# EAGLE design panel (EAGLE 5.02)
LAST_EDIT: 15.07; TITLE: xMedia P. - Sensors

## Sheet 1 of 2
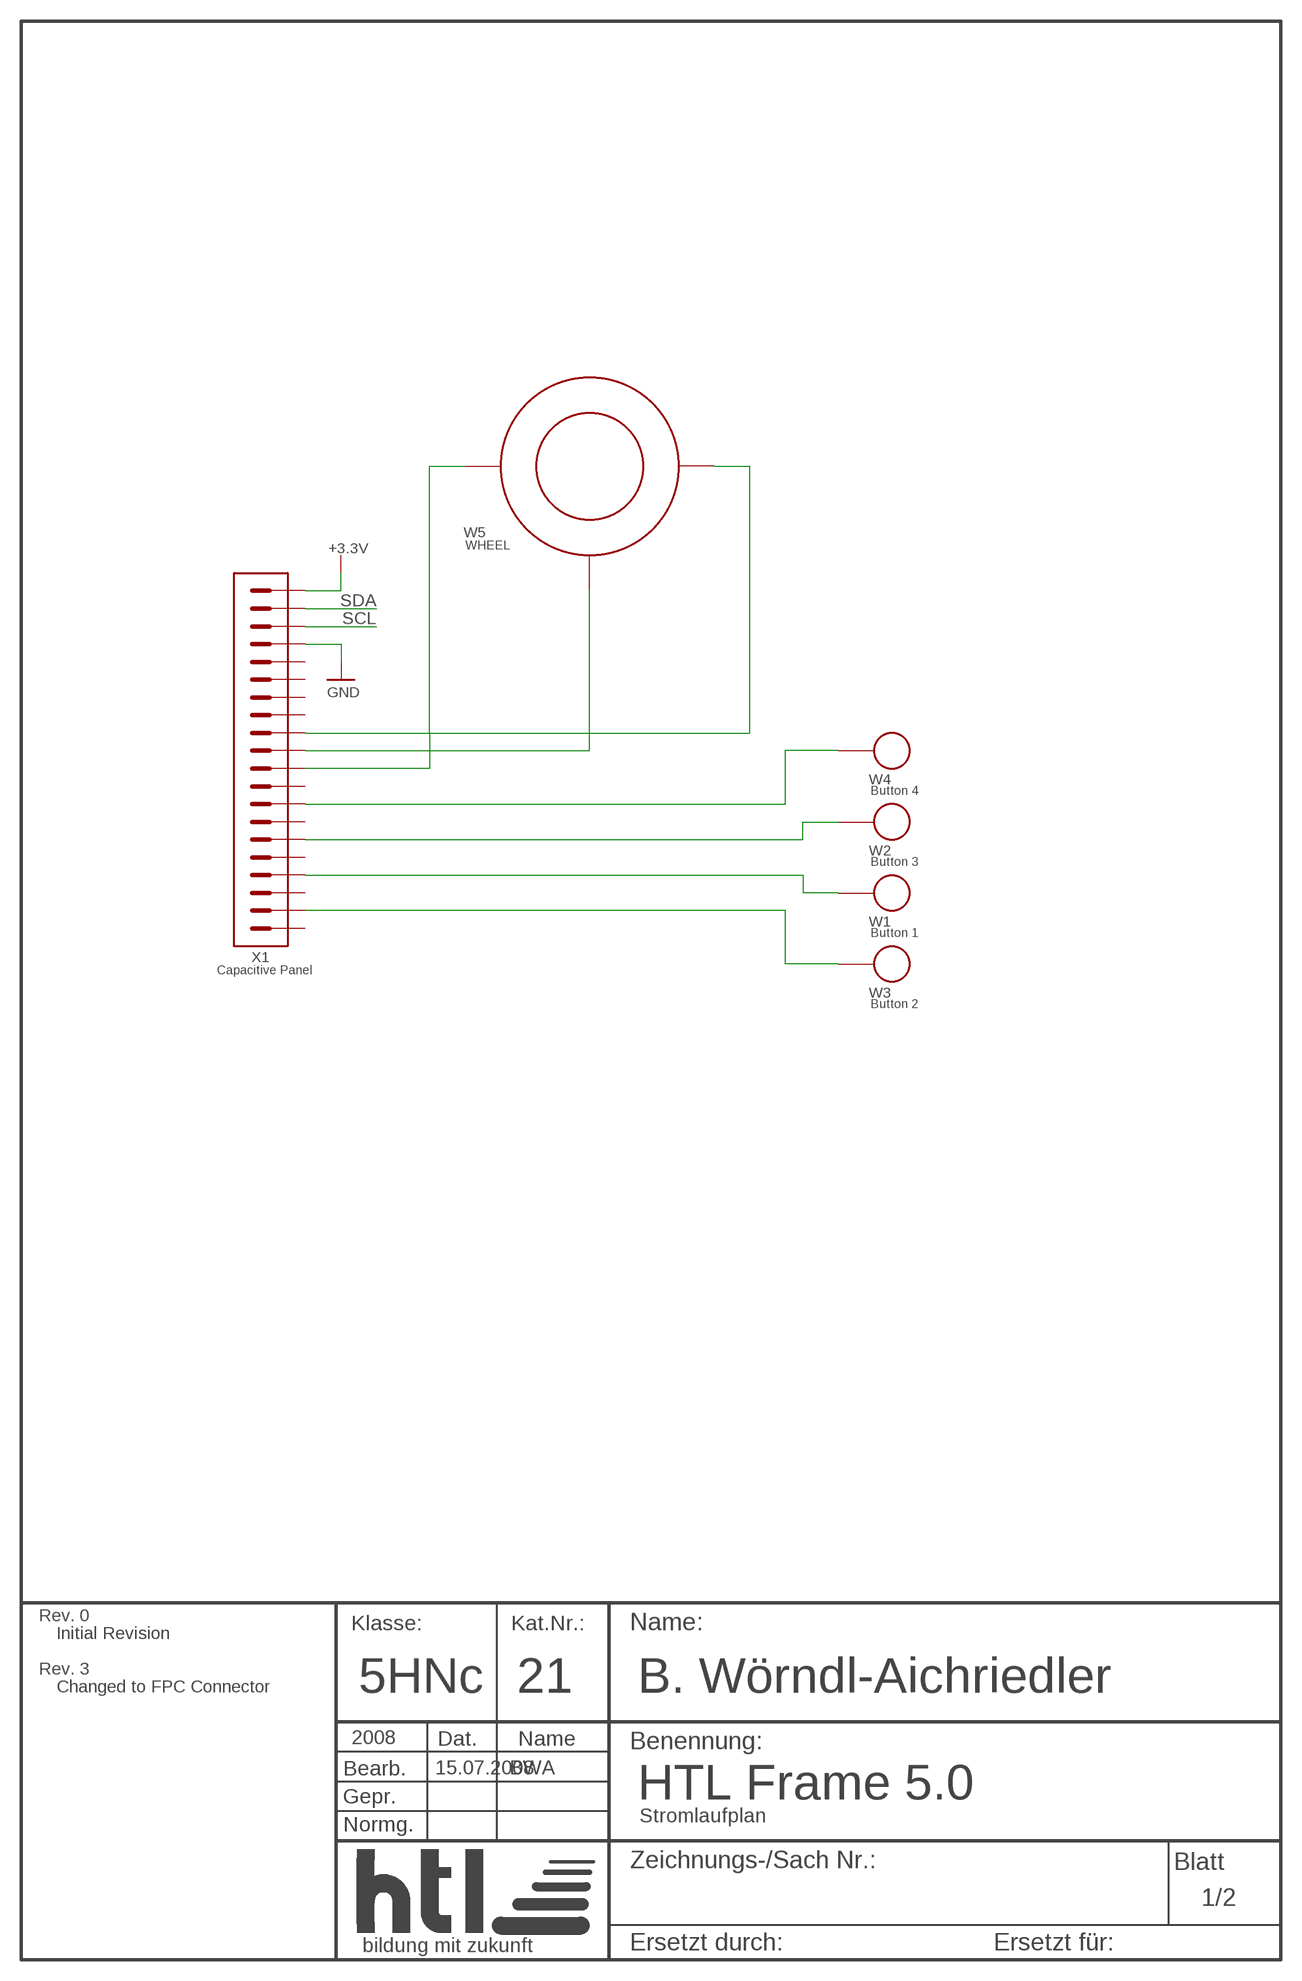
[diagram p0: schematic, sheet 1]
U$1 (HTL-FRAME-A4): CAT_NO: 21; CLASS: 5HNc; LAST_EDIT: 15.07.2008; SHORTNAME: BWA; SUBTITLE: Stromlaufplan; TITLE: HTL Frame 5.0; USERNAME: B. Wörndl-Aichriedler; YEAR: 2008

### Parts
W1  Button 1  CAP_BTN  [CAP_BTN]
W2  Button 3  CAP_BTN  [CAP_BTN]
W3  Button 2  CAP_BTN  [CAP_BTN]
W4  Button 4  CAP_BTN  [CAP_BTN]
W5  WHEEL  CAP_WHEEL  [CAP_WHEEL]
X1  Capacitive Panel  FPC-20-1MM  [FPC-20-1MM]

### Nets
+3.3V: X1.P$1 ; also sheet 2
GND: X1.P$4 ; also sheet 2
N$49: W5.1 X1.P$11
N$50: W5.3 X1.P$10
N$51: W5.2 X1.P$9
N$52: W4.P$1 X1.P$13
N$53: W2.P$1 X1.P$15
N$54: W1.P$1 X1.P$17
N$55: W3.P$1 X1.P$19
SCL: X1.P$3 ; also sheet 2
SDA: X1.P$2 ; also sheet 2
Unconnected: X1.P$5 X1.P$6 X1.P$7 X1.P$8 X1.P$12 X1.P$14 X1.P$16 X1.P$18 X1.P$20

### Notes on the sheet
- Rev. 0
- Initial Revision
- Rev. 3
- Changed to FPC Connector

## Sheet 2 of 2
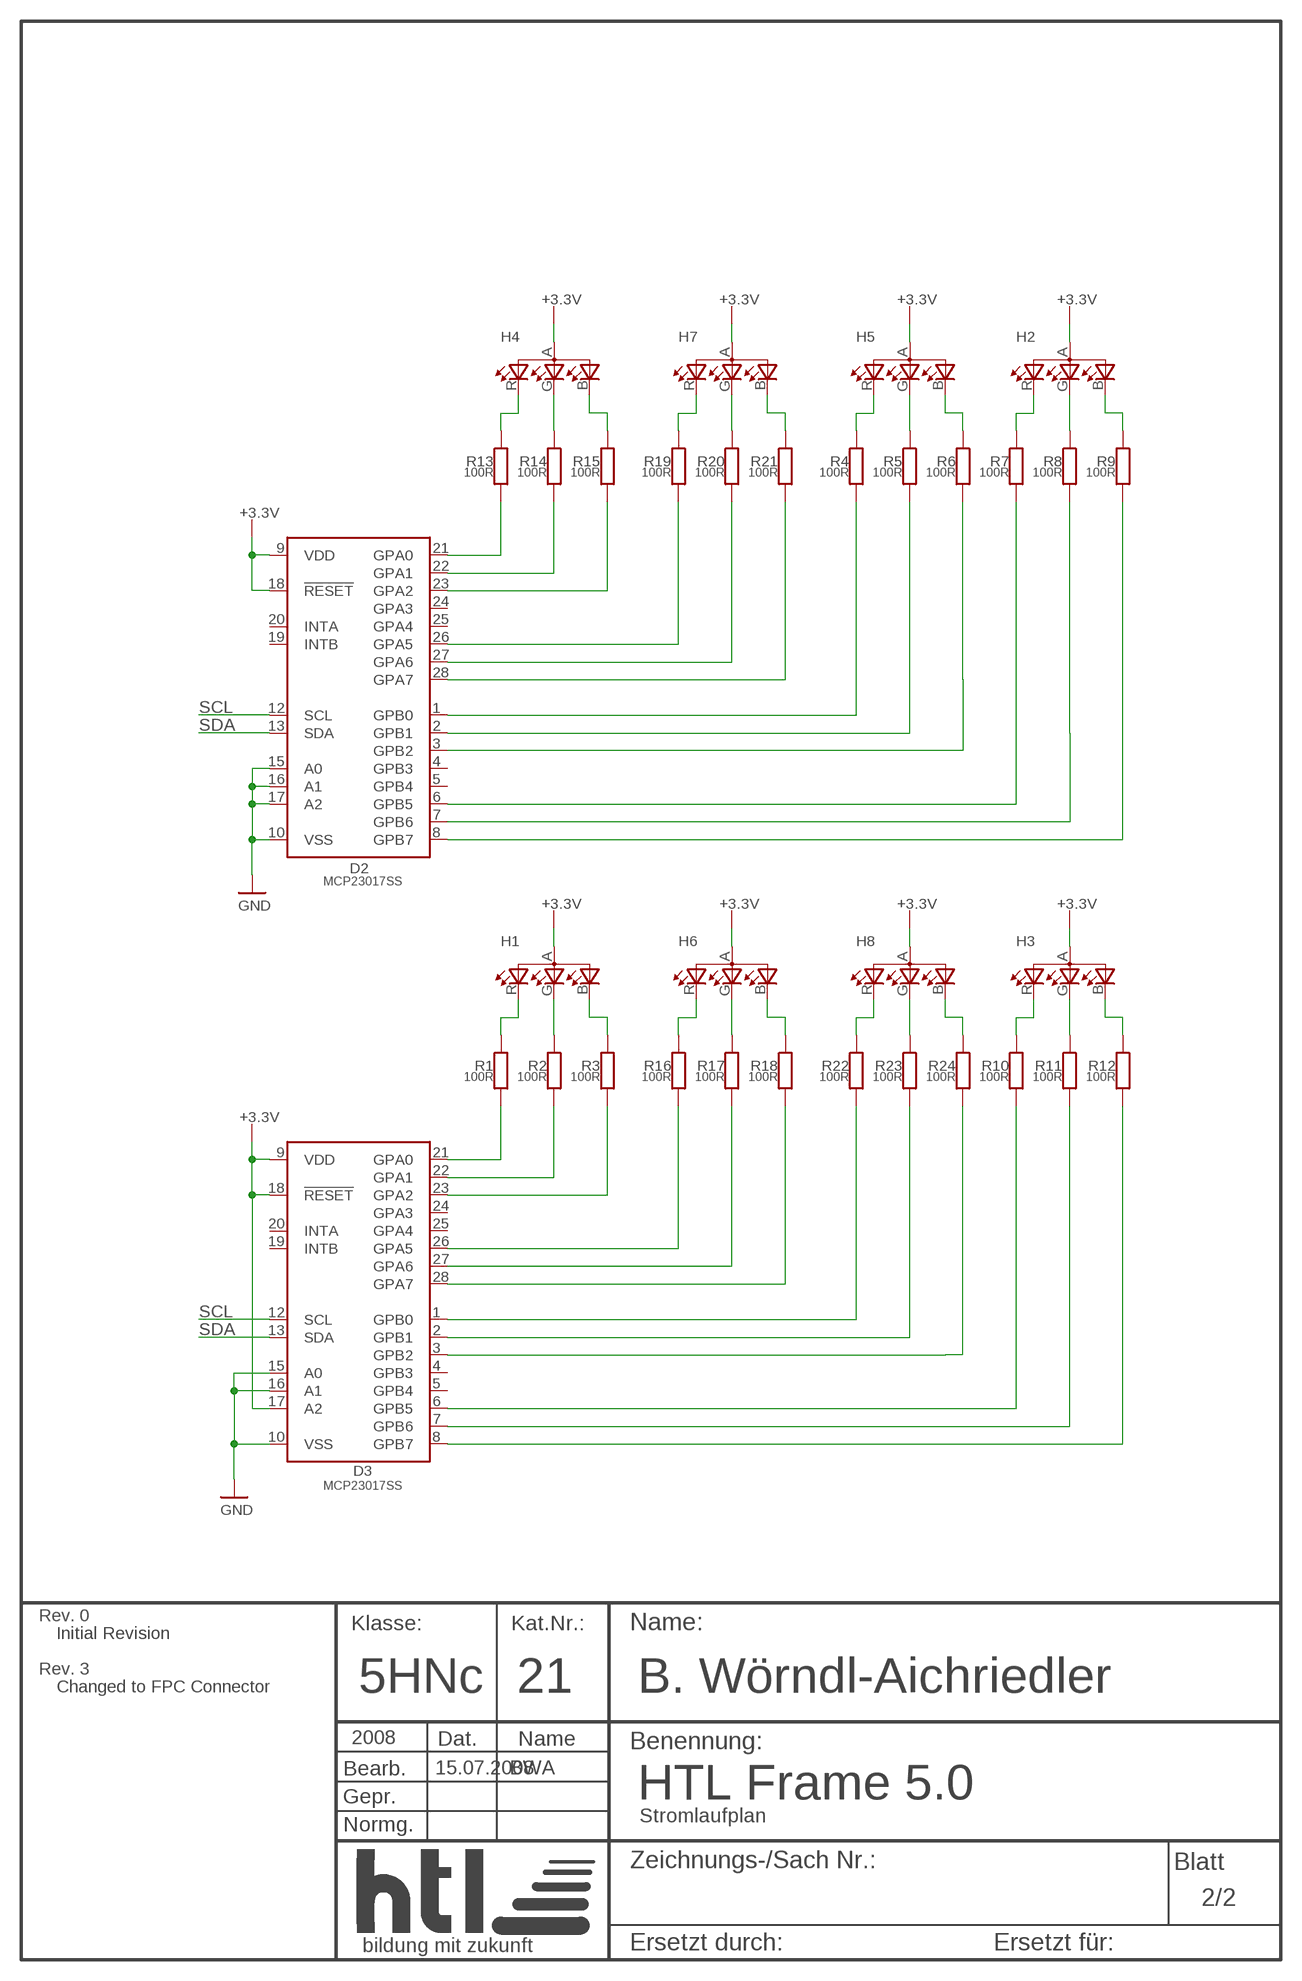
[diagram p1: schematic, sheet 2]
U$3 (HTL-FRAME-A4): CAT_NO: 21; CLASS: 5HNc; LAST_EDIT: 15.07.2008; SHORTNAME: BWA; SUBTITLE: Stromlaufplan; TITLE: HTL Frame 5.0; USERNAME: B. Wörndl-Aichriedler; YEAR: 2008

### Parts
D2  MCP23017SS  [SSOP28]
D3  MCP23017SS  [SSOP28]
H1  TOPLED-3BOTTOM_THRU  [P-LCC-4-SPECIAL]
H2  TOPLED-3BOTTOM_THRU  [P-LCC-4-SPECIAL]
H3  TOPLED-3BOTTOM_THRU  [P-LCC-4-SPECIAL]
H4  TOPLED-3BOTTOM_THRU  [P-LCC-4-SPECIAL]
H5  TOPLED-3BOTTOM_THRU  [P-LCC-4-SPECIAL]
H6  TOPLED-3BOTTOM_THRU  [P-LCC-4-SPECIAL]
H7  TOPLED-3BOTTOM_THRU  [P-LCC-4-SPECIAL]
H8  TOPLED-3BOTTOM_THRU  [P-LCC-4-SPECIAL]
R1  100R  R-EU_R0805  [R0805]
R2  100R  R-EU_R0805  [R0805]
R3  100R  R-EU_R0805  [R0805]
R4  100R  R-EU_R0805  [R0805]
R5  100R  R-EU_R0805  [R0805]
R6  100R  R-EU_R0805  [R0805]
R7  100R  R-EU_R0805  [R0805]
R8  100R  R-EU_R0805  [R0805]
R9  100R  R-EU_R0805  [R0805]
R10  100R  R-EU_R0805  [R0805]
R11  100R  R-EU_R0805  [R0805]
R12  100R  R-EU_R0805  [R0805]
R13  100R  R-EU_R0805  [R0805]
R14  100R  R-EU_R0805  [R0805]
R15  100R  R-EU_R0805  [R0805]
R16  100R  R-EU_R0805  [R0805]
R17  100R  R-EU_R0805  [R0805]
R18  100R  R-EU_R0805  [R0805]
R19  100R  R-EU_R0805  [R0805]
R20  100R  R-EU_R0805  [R0805]
R21  100R  R-EU_R0805  [R0805]
R22  100R  R-EU_R0805  [R0805]
R23  100R  R-EU_R0805  [R0805]
R24  100R  R-EU_R0805  [R0805]

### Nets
+3.3V: D2.9(VDD) D2.18(!RESET) D3.9(VDD) D3.17(A2) D3.18(!RESET) H1.A(A2) H2.A(A2) H3.A(A2) H4.A(A2) H5.A(A2) H6.A(A2) H7.A(A2) H8.A(A2) ; also sheet 1
GND: D2.10(VSS) D2.15(A0) D2.16(A1) D2.17(A2) D3.10(VSS) D3.15(A0) D3.16(A1) ; also sheet 1
N$1: H1.R(CRED) R1.1
N$2: H1.G(CGREEN) R2.1
N$3: H1.B(CBLUE) R3.1
N$4: D3.21(GPA0) R1.2
N$5: D3.22(GPA1) R2.2
N$6: D3.23(GPA2) R3.2
N$7: H5.R(CRED) R4.1
N$8: H5.G(CGREEN) R5.1
N$9: H5.B(CBLUE) R6.1
N$10: D2.1(GPB0) R4.2
N$11: D2.2(GPB1) R5.2
N$12: D2.3(GPB2) R6.2
N$13: H2.R(CRED) R7.1
N$14: H2.G(CGREEN) R8.1
N$15: H2.B(CBLUE) R9.1
N$16: D2.6(GPB5) R7.2
N$17: D2.7(GPB6) R8.2
N$18: D2.8(GPB7) R9.2
N$19: H3.R(CRED) R10.1
N$20: H3.G(CGREEN) R11.1
N$21: H3.B(CBLUE) R12.1
N$22: D3.6(GPB5) R10.2
N$23: D3.7(GPB6) R11.2
N$24: D3.8(GPB7) R12.2
N$25: H4.R(CRED) R13.1
N$26: H4.G(CGREEN) R14.1
N$27: H4.B(CBLUE) R15.1
N$28: D2.21(GPA0) R13.2
N$29: D2.22(GPA1) R14.2
N$30: D2.23(GPA2) R15.2
N$31: H6.R(CRED) R16.1
N$32: H6.G(CGREEN) R17.1
N$33: H6.B(CBLUE) R18.1
N$34: D3.26(GPA5) R16.2
N$35: D3.27(GPA6) R17.2
N$36: D3.28(GPA7) R18.2
N$37: H7.R(CRED) R19.1
N$38: H7.G(CGREEN) R20.1
N$39: H7.B(CBLUE) R21.1
N$40: D2.26(GPA5) R19.2
N$41: D2.27(GPA6) R20.2
N$42: D2.28(GPA7) R21.2
N$43: H8.R(CRED) R22.1
N$44: H8.G(CGREEN) R23.1
N$45: H8.B(CBLUE) R24.1
N$46: D3.1(GPB0) R22.2
N$47: D3.2(GPB1) R23.2
N$48: D3.3(GPB2) R24.2
SCL: D2.12(SCL) D3.12(SCL) ; also sheet 1
SDA: D2.13(SDA) D3.13(SDA) ; also sheet 1
Unconnected: D2.4(GPB3) D2.5(GPB4) D2.19(INTB) D2.20(INTA) D2.24(GPA3) D2.25(GPA4) D3.4(GPB3) D3.5(GPB4) D3.19(INTB) D3.20(INTA) D3.24(GPA3) D3.25(GPA4)

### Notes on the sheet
- Rev. 0
- Initial Revision
- Rev. 3
- Changed to FPC Connector

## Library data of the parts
D2 D3 = xmedia:MCP23017: http://ww1.microchip.com/downloads/en/DeviceDoc/21952a.pdf Source: http://ww1.microchip.com/downloads/en/DeviceDoc/21952a.pdf
H1-H8 = xmedia:TOPLED-3: OSRAM - Hyper Multi TOPLED® (RGB) LB E673, LV E673, LT E673 - Power TOPLED® Enhanced optical Power LED (HOP2000) LS E67B, LA E67B, LO E67B, LY E67B - Hyper Multi TOPLED® Enhanced optical Power LED (HOP2000 / ATON®) LATB T66B - Hyper Multi TOPLED® Hyper-Bright LED LATB T686 Source: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
R1-R24 = xmedia-rcl:R-EU_: RESISTOR, European symbol
W1-W4 = xmedia:CAP_BTN
W5 = xmedia:CAP_WHEEL
X1 = xmedia:FPC-20-1MM

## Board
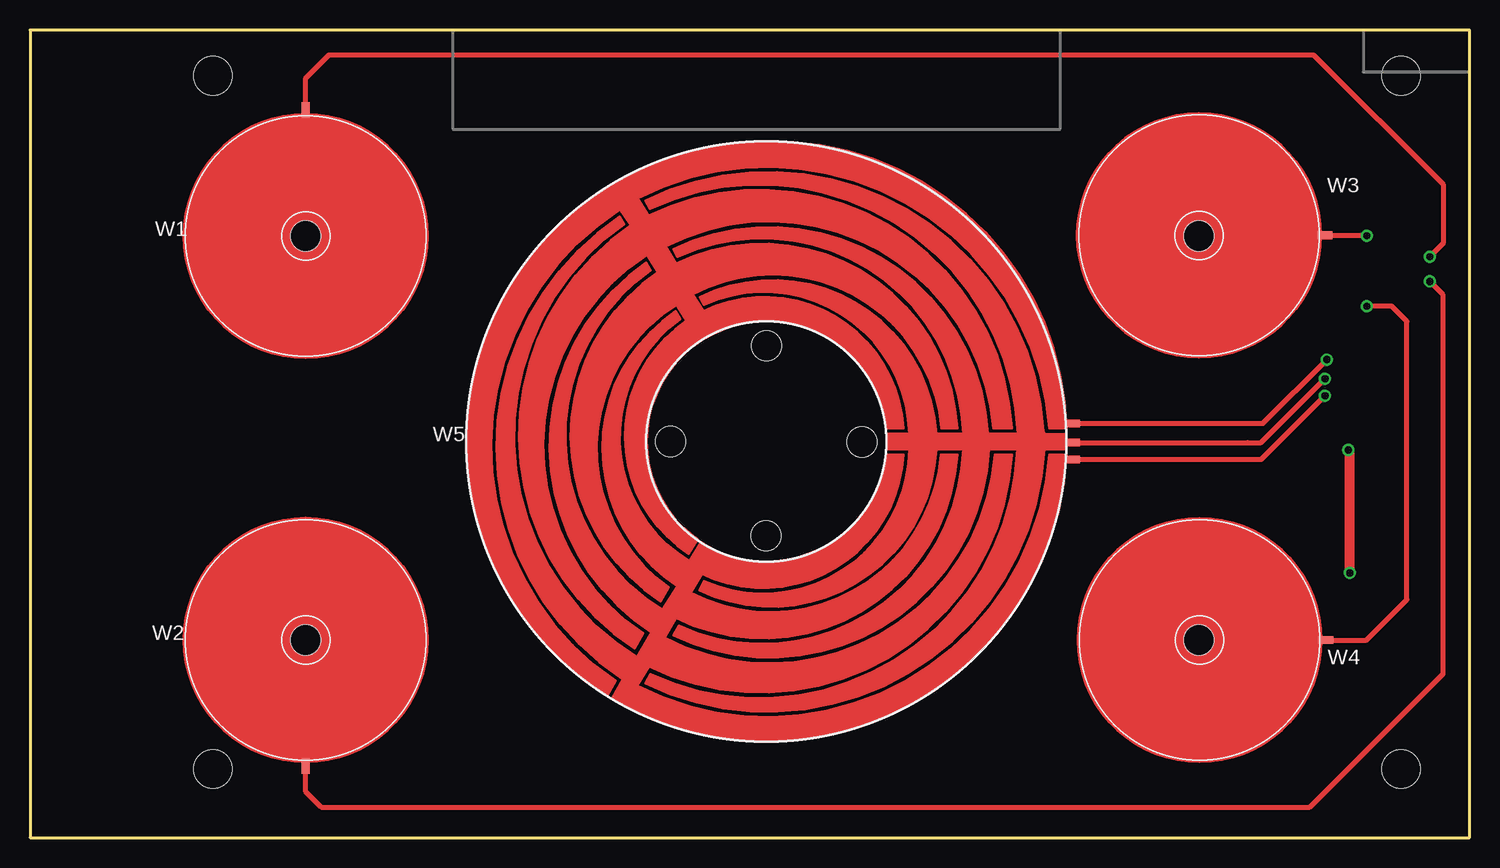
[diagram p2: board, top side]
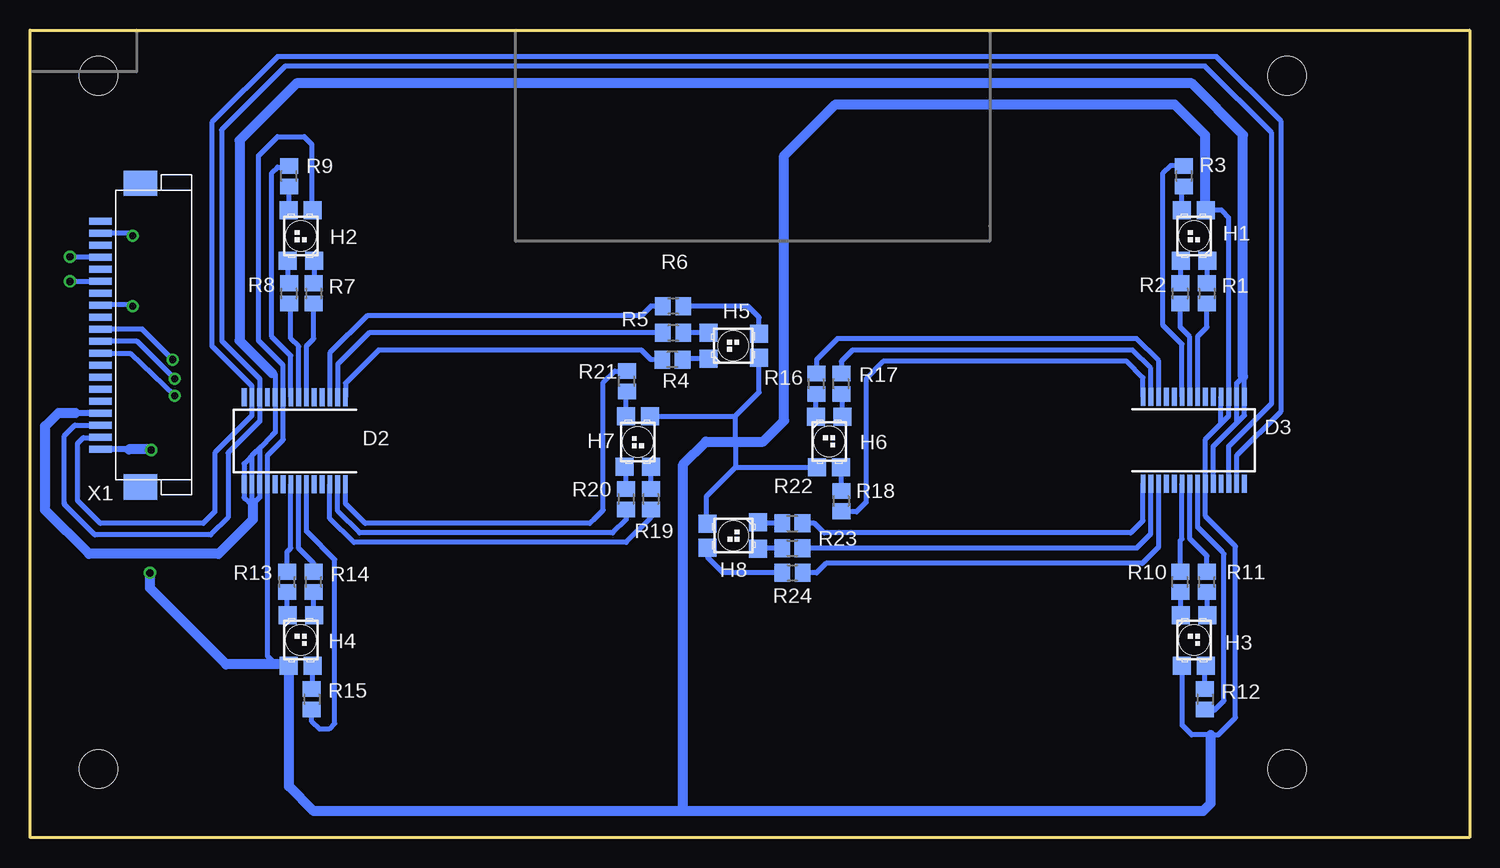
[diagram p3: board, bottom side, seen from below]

Size 120.02 x 67.31 mm. Coordinates in mm from the lower left corner, seen from the top.
Outline: 0,0 120.02,0 120.02,67.31 0,67.31 0,0
Copper layers (1+16): Top 0.035mm / dielectric 1.6mm / Bottom 0.035mm
Design rules "multipcb": minimum track width 6mil, minimum drill 0.4mm, track to track 6mil, track to pad 6mil, pad to pad 6mil, via to via 6mil, smd to smd 6mil, copper to edge 20mil, drill to drill 10mil, minimum pad ring 8mil, minimum via ring 8mil, stop-mask expansion 4mil, vias tented up to drill 18mil, thermal gap 10mil
Holes 3.2 mm at 114.3,63.5 15.24,63.5 15.24,5.71 114.3,5.71

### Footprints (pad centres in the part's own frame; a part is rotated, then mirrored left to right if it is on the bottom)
SSOP28 = smd 0.4 x 1.5: 1 -4.225,-3.625; 2 -3.575,-3.625; 3 -2.925,-3.625; 4 -2.275,-3.625; 5 -1.625,-3.625; 6 -0.975,-3.625; 7 -0.325,-3.625; 8 0.325,-3.625; 9 0.975,-3.625; 10 1.625,-3.625; 11 2.275,-3.625; 12 2.925,-3.625; 13 3.575,-3.625; 14 4.225,-3.625; 15 4.225,3.625; 16 3.575,3.625; 17 2.925,3.625; 18 2.275,3.625; 19 1.625,3.625; 20 0.975,3.625; 21 0.325,3.625; 22 -0.325,3.625; 23 -0.975,3.625; 24 -1.625,3.625; 25 -2.275,3.625; 26 -2.925,3.625; 27 -3.575,3.625; 28 -4.225,3.625
P-LCC-4-SPECIAL = smd 1.5 x 1.5 bottom: A -1,2.15; B 1,2.15; G 1.1,-2.05; R -1.1,-2.05 | hole 2.5: 0,0
R0805 = smd 1.3 x 1.5: 1 -0.85,0; 2 0.85,0
CAP_BTN = smd 1.27 x 0.635: P$1 -10.5,0
CAP_WHEEL = smd 0.635 x 1.27: 1 -1.5,25.5; 2 1.5,25.5; 3 0.1,25.5
FPC-20-1MM = smd 0.6 x 1.9: P$1 0,0; P$2 1,0; P$3 2,0; P$4 3,0; P$5 4,0; P$6 5,0; P$7 6,0; P$8 7,0; P$9 8,0; P$10 9,0; P$11 10,0; P$12 11,0; P$13 12,0; P$14 13,0; P$15 14,0; P$16 15,0; P$17 16,0; P$18 17,0; P$19 18,0; P$20 19,0 | smd 2.1 x 2.8: P$21 22.15,-3.35; P$22 -3.15,-3.35

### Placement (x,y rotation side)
D2  97.94,33.07 180 bottom
D3  23.01,33.12 0 bottom
DRILEGEND  [DRILEGEND]  not placed on the board
H1  22.98,50.14 0 top
H2  97.43,50.14 0 top
H3  22.98,16.48 180 top
H4  97.43,16.48 180 top
H5  61.39,41 90 top
H6  53.39,33.02 180 top
H7  69.34,32.97 0 top
H8  61.37,25.17 270 top
MEASURE  [MEASURE]  0,0 0 top
R1  21.91,45.36 270 bottom
R2  24.13,45.36 270 bottom
R3  23.81,55.13 90 bottom
R4  66.47,39.85 180 bottom
R5  66.4,42.07 180 bottom
R6  66.4,44.29 180 bottom
R7  96.36,45.36 270 bottom
R8  98.42,45.36 270 bottom
R9  98.42,55.13 90 bottom
R10  24.13,21.32 90 bottom
R11  21.91,21.32 90 bottom
R12  22.07,11.54 270 bottom
R13  98.58,21.32 90 bottom
R14  96.36,21.32 90 bottom
R15  96.52,11.54 270 bottom
R16  54.45,37.83 90 bottom
R17  52.39,37.83 90 bottom
R18  52.39,28.05 270 bottom
R19  68.26,28.21 270 bottom
R20  70.33,28.21 270 bottom
R21  70.26,38.04 90 bottom
R22  56.47,26.19 0 bottom
R23  56.47,24.13 0 bottom
R24  56.45,22.09 0 bottom
W1  22.98,50.14 270 top
W2  22.98,16.48 90 top
W3  97.45,50.2 180 top
W4  97.5,16.47 180 top
W5  61.39,33.02 270 top
X1  114.14,32.38 90 bottom

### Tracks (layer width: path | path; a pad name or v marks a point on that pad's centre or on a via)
+3.3V  (via drill 0.6)
  Top 0.813: v110.01,22.07 110.01,32.36 v109.91,32.31
  Bottom 0.406: 61.2,30.87 H6.A | 61.2,30.87 63.66,28.42 63.66,26.51 63.5,26.35 63.52,26.34 H8.A | H5.A 59.24,37.12 61.28,35.08 | H7.A 68.39,35.12 68.58,34.92 68.42,35.08 61.28,35.08 | 61.2,30.87 61.2,33.01 61.2,35.01 61.28,35.08 | D3.18 20.73,34.51 20.8,34.45 | 20.8,34.45 21.43,33.81 22.03,33.21 D3.9 22.03,26.79 19.68,24.45 19.53,24.29 19.53,10 20.95,8.57 21.59,8.57 23.18,8.57 23.97,9.37 23.97,13.97 24.13,14.13 24.08,14.18 H3.A | H4.A 98.43,14.3 98.42,14.29 98.58,14.45 99.06,14.45 99.54,14.45 100.22,15.13 D2.18 100.22,31.86 98.9,33.18 98.9,36.51 98.92,36.53 D2.9 98.92,39.39 100.97,41.43 100.97,56.83 99.38,58.42 97.16,58.42 96.52,57.78 96.52,52.39 96.43,52.3 H2.A | 20.7,52.29 H1.A | 20.7,52.29 20.64,52.23 20.08,51.67 D3.17 20.08,35.16 20.8,34.45 | 20.7,52.29
  Bottom 0.508: X1.P$1 113.98,32.38 113.96,32.36 111.77,32.36
  Bottom 0.813: 65.56,2.22 22.23,2.22 21.59,2.86 21.59,8.41 21.59,8.57 | 65.56,2.22 96.36,2.22 | 65.56,2.22 65.56,2.38 65.56,31.11 63.67,33.01 61.2,33.01 58.9,33.01 57.15,34.77 57.15,56.83 52.86,61.12 24.61,61.12 22.07,58.58 22.07,52.7 22.07,52.39 | 96.36,2.22 | 96.36,2.22 98.42,4.29 98.42,14.29 | 99.06,14.45 103.66,14.45 110.01,20.8 v110.01,22.07 | v109.91,32.31 110.08,32.31 109.98,32.36 111.77,32.36
GND
  Bottom 0.406: D3.10 21.38,32.59 21.38,32.61 | 19.43,34.61 19.43,34.54 19.44,34.54 21.38,32.61 | 19.43,34.61 D3.16 19.43,37.88 19.21,38.1 18.89,38.42 18.78,38.53 D3.15 18.78,35.19 19.37,34.61 19.43,34.61 | 100.81,32.54 99.85,33.5 99.57,33.78 D2.10 99.57,38.61 99.85,38.89 99.93,38.81 | 100.81,32.54 100.87,32.48 D2.17 100.87,28.36 101.28,27.94 101.44,27.94 | 101.44,27.94 101.76,27.94 102.08,28.26 102.17,28.35 D2.15 102.17,31.18 101.28,32.07 | 101.44,27.94 101.52,28.02 D2.16 101.52,31.83 101.28,32.07 | 21.38,32.61 | 100.97,32.38 101.28,32.07 | 100.97,32.38 | 100.81,32.54 100.97,32.38
  Bottom 0.508: 114.14,35.4 | 114.14,35.4 X1.P$4 | 116.2,35.4 114.14,35.4
  Bottom 0.813: 101.44,27.94 101.44,26.51 104.3,23.65 115.09,23.65 118.75,27.3 118.75,34.29 117.63,35.4 116.2,35.4 | 18.89,38.42 18.89,58.58 23.18,62.87 97.79,62.87 102.55,58.1 102.55,41.43 99.93,38.81 99.85,38.73
N$1
  Bottom 0.406: H1.R 21.88,47.97 21.91,48.26 R1.1
N$2
  Bottom 0.406: H1.G 24.28,48.09 24.29,48.26 24.13,48.58 R2.1
N$3
  Bottom 0.406: R3.1 23.96,54.12 23.97,54.29 23.98,54.14 H1.B
N$4
  Bottom 0.406: D3.21 22.68,41.77 21.91,42.55 21.91,44.61 R1.2
N$5
  Bottom 0.406: D3.22 23.33,41.75 24.13,42.55 24.13,44.45 | 24.13,44.45 | 24.13,44.45 R2.2
N$6
  Bottom 0.406: D3.23 23.98,41.13 25.56,42.7 25.56,55.4 24.92,56.04 24.13,56.04 23.87,55.98 R3.2
N$7
  Bottom 0.406: R4.1 65.56,39.85 65.51,39.9 H5.R
N$8
  Bottom 0.406: R5.1 65.88,42.07 65.86,42.1 H5.G
N$9
  Bottom 0.406: 58.9,41.91 59.05,42.07 59.13,42 H5.B 59.24,43.37 60.17,44.29 65.56,44.29 R6.1
N$10
  Bottom 0.406: D2.1 93.72,37.89 91.76,39.85 90.96,40.64 69.06,40.64 68.26,39.85 67.47,39.85 R4.2
N$11
  Bottom 0.406: D2.2 94.37,39.46 91.76,42.07 67.47,42.07 R5.2
N$12
  Bottom 0.406: D2.3 95.02,40.4 91.92,43.5 69.06,43.5 68.26,44.29 R6.2
N$13
  Bottom 0.406: R7.1 96.36,46.35 96.33,46.38 H2.R
N$14
  Bottom 0.406: R8.1 98.42,46.2 98.53,46.31 H2.G
N$15
  Bottom 0.406: H2.B 98.49,52.29 98.58,52.39 98.42,52.55 R9.1
N$16
  Bottom 0.406: D2.6 96.97,40.99 96.36,41.59 96.36,44.45 R7.2
N$17
  Bottom 0.406: D2.7 97.62,40.94 98.27,41.59 98.27,44.29 98.42,44.45 R8.2
N$18
  Bottom 0.406: D2.8 98.27,40.16 99.85,41.75 99.85,55.4 99.38,55.88 98.74,55.88 98.64,55.98 R9.2
N$19
  Bottom 0.406: R10.1 24.13,20.32 24.08,20.27 H3.R
N$20
  Bottom 0.406: R11.1 21.91,20.32 21.88,20.13 H3.G
N$21
  Bottom 0.406: H3.B 21.98,13.88 22.07,13.81 R12.1
N$22
  Bottom 0.406: D3.6 23.98,24.91 24.13,24.77 24.13,22.07 R10.2
N$23
  Bottom 0.406: D3.7 23.33,24.92 21.91,23.5 21.91,22.07 R11.2
N$24
  Bottom 0.406: D3.8 22.68,25.86 20.64,23.81 20.48,23.65 20.48,11.43 21.27,10.64 21.91,10.64 22.01,10.54 R12.2
N$25
  Bottom 0.406: H4.R 98.53,18.62 98.58,18.73 R13.1
N$26
  Bottom 0.406: H4.G 96.33,18.76 96.36,18.73 96.36,18.89 R14.1
N$27
  Bottom 0.406: R15.1 96.52,12.22 96.43,12.3 H4.B
N$28
  Bottom 0.406: D2.21 98.27,24.13 98.58,23.81 98.58,22.38 98.58,22.23 98.53,22.17 R13.2
N$29
  Bottom 0.406: D2.22 97.62,24.12 96.36,22.86 96.36,22.07 96.36,22.23 R14.2
N$30
  Bottom 0.406: R15.2 96.52,9.68 95.89,9.05 95.09,9.05 94.61,9.53 94.61,23.18 96.84,25.4 96.97,25.53 D2.23
N$31
  Bottom 0.406: R16.1 | R16.1 | H6.R 54.49,36.95 R16.1
N$32
  Bottom 0.406: R17.1 52.39,36.83 52.29,36.73 H6.G
N$33
  Bottom 0.406: H6.B 52.39,30.64 R18.1
N$34
  Bottom 0.406: D3.26 25.93,39.74 27.78,41.59 52.7,41.59 54.45,39.85 54.45,38.89 | 54.45,38.89 | 54.45,38.89 R16.2
N$35
  Bottom 0.406: D3.27 26.58,39.12 28.1,40.64 51.44,40.64 52.39,39.69 52.39,38.89 52.23,38.73 52.29,38.68 R17.2
N$36
  Bottom 0.406: D3.28 27.23,38.34 28.57,39.69 48.9,39.69 50.32,38.26 50.32,27.94 51.12,27.15 52.55,27.15 52.49,27.2 R18.2
N$37
  Bottom 0.406: 68.26,30.8 68.24,30.82 H7.R | R19.1 68.26,30.8 | 68.26,30.8
N$38
  Bottom 0.406: 70.33,30.8 H7.G | R20.1 70.33,30.8 | 70.33,30.8
N$39
  Bottom 0.406: R21.1 70.28,37.19 70.33,37.15 70.34,37.13 H7.B
N$40
  Bottom 0.406: D2.26 95.02,26.6 93.03,24.61 70.33,24.61 68.26,26.67 68.26,27.15 | 68.26,27.15 | R19.2 68.26,27.15
N$41
  Bottom 0.406: R20.2 70.33,26.51 71.44,25.4 92.55,25.4 94.37,27.22 D2.27
N$42
  Bottom 0.406: R21.2 71.28,38.89 72.23,37.94 72.23,27.3 73.03,26.51 73.18,26.35 73.34,26.19 92.08,26.19 92.23,26.35 | D2.28 93.72,27.84 92.23,26.35 | 92.23,26.35
N$43
  Bottom 0.406: 59.21,26.19 59.29,26.27 H8.R | R22.1 59.21,26.19 | 59.21,26.19
N$44
  Bottom 0.406: H8.G 59.27,24.07 59.21,24.13 R23.1
N$45
  Bottom 0.406: R24.1 62.25,22.09 63.5,23.34 63.5,24.13 63.52,24.15 H8.B
N$46
  Bottom 0.406: R22.2 54.61,26.19 53.82,25.4 28.26,25.4 27.62,26.04 27.23,26.43 D3.1
N$47
  Bottom 0.406: D3.2 26.58,25.33 27.78,24.13 55.72,24.13 R23.2
N$48
  Bottom 0.406: D3.3 25.93,24.23 27.3,22.86 53.66,22.86 54.45,22.07 55.88,22.07 55.86,22.09 R24.2
N$49  (via drill 0.6)
  Top 0.406: W5.1 102.78,34.52 v108.11,39.85
  Bottom 0.406: v108.11,39.85 110.65,42.39 113.98,42.39 114.3,42.39 X1.P$11
N$50  (via drill 0.6)
  Top 0.406: W5.3 101.5,32.92 102.61,32.92 v107.95,38.26
  Bottom 0.406: v107.95,38.26 107.97,38.26 111.07,41.36 113.91,41.36 113.98,41.43 114.14,41.43 X1.P$10
N$51  (via drill 0.6)
  Top 0.406: W5.2 102.64,31.52 v107.95,36.83
  Bottom 0.406: v107.95,36.83 111.6,40.32 | 111.6,40.32 114.14,40.32 X1.P$9 | 111.6,40.32
N$52  (via drill 0.6)
  Top 0.406: W4.P$1 111.4,16.47 114.78,19.84 114.78,43.02 113.51,44.29 v111.44,44.29
  Bottom 0.406: 114.62,44.3 114.5,44.41 114.3,44.41 | 114.3,44.41 111.56,44.41 v111.44,44.29 | 114.3,44.41 114.3,44.45 114.23,44.38 X1.P$13
N$53  (via drill 0.6)
  Top 0.406: W2.P$1 22.98,3.85 24.29,2.54 106.68,2.54 109.7,5.56 | 109.7,5.56 | 109.7,5.56 117.79,13.65 117.79,45.24 v116.68,46.35
  Bottom 0.406: X1.P$15 114.3,46.35 114.14,46.35 v116.68,46.35
N$54  (via drill 0.6)
  Top 0.406: W1.P$1 22.98,63.3 24.92,65.25 107,65.25 117.79,54.45 117.79,49.53 v116.68,48.42
  Bottom 0.406: 114.3,48.42 | 114.3,48.42 X1.P$17 | v116.68,48.42 114.3,48.42
N$55  (via drill 0.6)
  Top 0.406: W3.P$1 111.4,50.2 v111.44,50.16
  Bottom 0.406: 111.44,50.24 v111.44,50.16 111.63,50.35 114.66,50.35 114.17,50.35 114.14,50.32 | 114.62,50.32 114.56,50.38 X1.P$19 114.14,50.32 | 114.14,50.32
SCL
  Bottom 0.406: 19.84,32.86 20,32.7 | 19.84,32.86 16.51,36.2 16.51,58.74 22.07,64.29 98.74,64.29 104.04,58.99 104.03,41.4 100.87,38.24 D2.12 100.87,34.7 101.76,33.81 103.5,32.07 103.5,26.67 104.93,25.24 114.62,25.24 116.2,26.83 117.16,27.78 117.16,27.94 117.16,33.5 116.27,34.38 X1.P$3 | 19.84,32.86 | D3.12 20.08,32.62 19.84,32.86
SDA
  Bottom 0.406: D3.13 19.43,31.84 19.37,31.91 15.72,35.56 15.72,59.69 21.11,65.09 99.38,65.09 104.85,59.61 104.86,40.99 101.52,37.65 D2.13 101.52,35.17 101.6,35.08 102.08,34.61 104.62,32.07 104.62,27.15 105.57,26.19 114.14,26.19 116.05,28.1 116.05,32.86 115.57,33.34 114.3,33.34 114.25,33.38 X1.P$2

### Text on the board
tDocu: xMedia - Capacitive Panel | Top | Version 3.33 Final | Bernhard Wörndl-Aichriedler (bwa) | www.berniwa.com / bwa@berniwa.com
bDocu: Bottom | Media | X
_tsilk: xMedia - Capacitive Panel | xMedia - Capacitive Panel | Top | Top | Version 0.33 Prototype | Version 0.33 Prototype | Bernhard Wörndl-Aichriedler (bwa) | Bernhard Wörndl-Aichriedler (bwa) | 1 | 1 | www.berniwa.com / bwa@berniwa.com | www.berniwa.com / bwa@berniwa.com | W3 | W3 | Button 2 | Button 2 | W1 | W1 | Button 1 | Button 1 | X2 | X2 | W5 | W5 | 12 | 12 | WHEEL | WHEEL | 1 | 1 | X3 | X3 | W2 | W2 | Button 3 | Button 3 | 4 | 4 | W4 | W4 | Button 4 | Button 4
_bsilk: Bottom | Bottom | Media | R3 | R3 | R9 | R9 | 100R | 100R | 100R | 100R | X | H1 | H1 | R6 | R6 | H2 | H2 | R2 | R2 | 100R | 100R | R8 | R8 | R1 | R1 | 100R | 100R | H5 | H5 | R7 | R7 | 100R | 100R | 100R | 100R | R5 | R5 | 100R | 100R | 100R | 100R | R21 | R21 | R4 | R4 | R17 | R17 | R16 | R16 | 100R | 100R | 100R | 100R | 100R | 100R | 100R | 100R | D3 | D3 | MCP23017SS | MCP23017SS | H6 | H6 | H7 | H7 | R20 | R20 | R22 | R22 | R18 | R18 | 100R | 100R | D2 | D2 | 100R | 100R | 100R | 100R | R19 | R19 | MCP23017SS | MCP23017SS | 100R | 100R | R23 | R23 | 100R | 100R | R13 | R13 | R11 | R11 | R10 | R10 | H8 | H8 | R14 | R14 | 100R | 100R | 100R | 100R | 100R | 100R | R24 | R24 | 100R | 100R | 100R | 100R | H4 | H4 | H3 | H3 | R12 | R12 | R15 | R15 | 100R | 100R | 100R | 100R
